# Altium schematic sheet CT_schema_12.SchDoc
size 382 x 278 mm
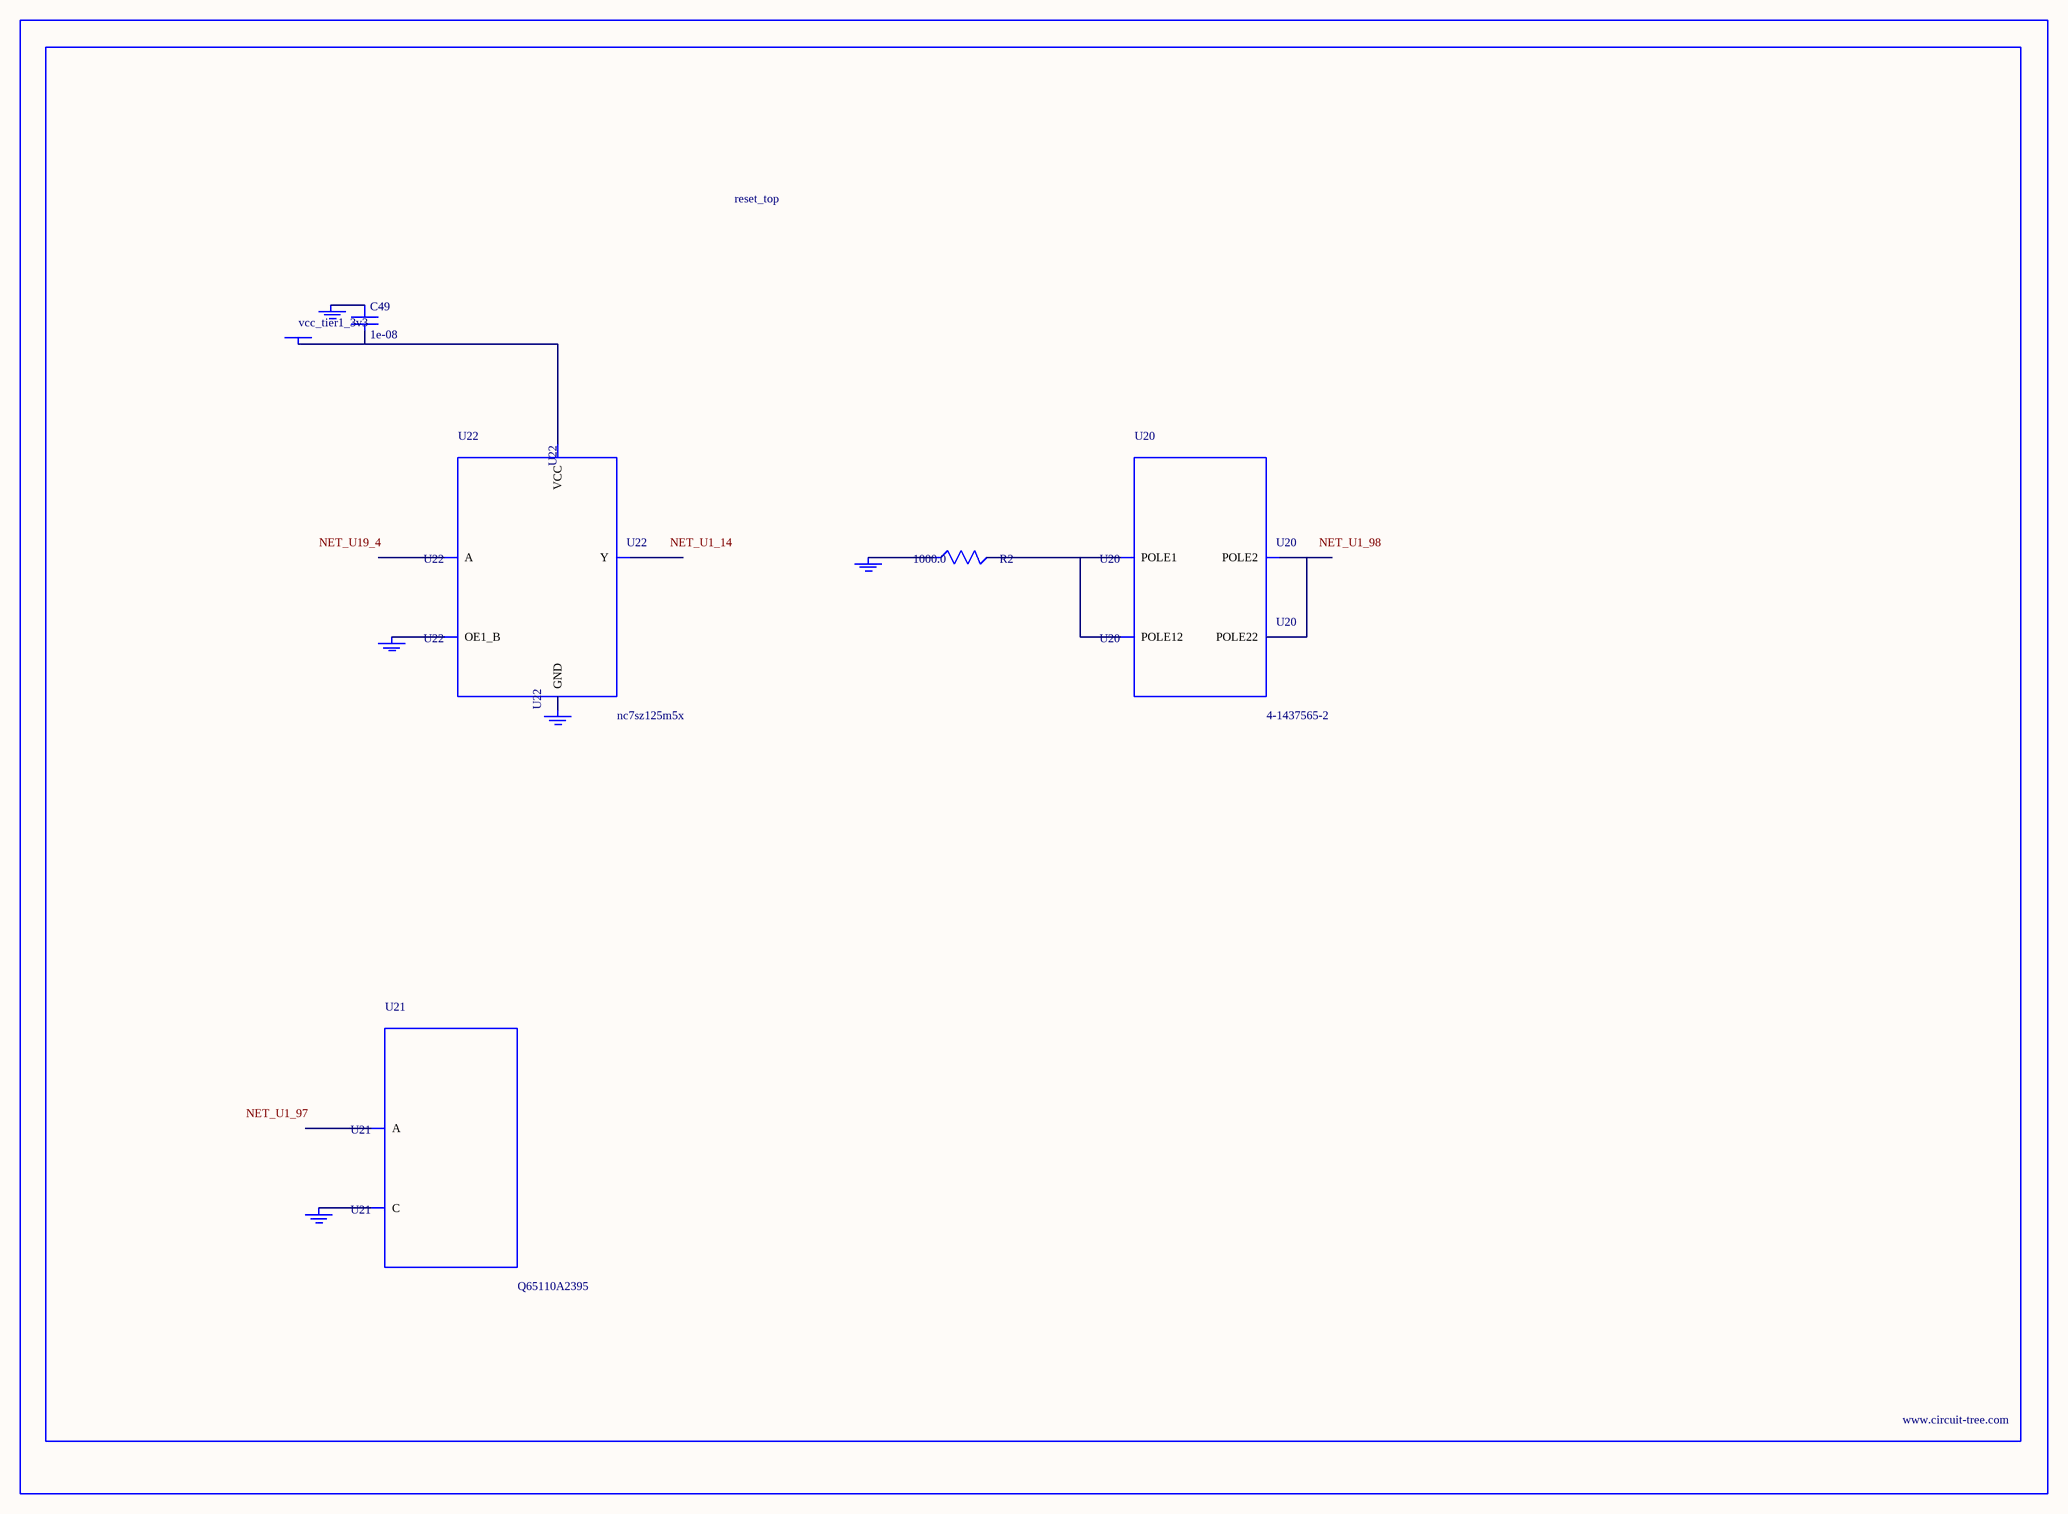
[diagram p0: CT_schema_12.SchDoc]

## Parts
BORDER11  (no value)
C49  1e-08  [C0402]
GND_INSTANCE_11_0  (no value)
GND_INSTANCE_11_1  (no value)
GND_INSTANCE_11_2  (no value)
GND_INSTANCE_11_3  (no value)
GND_INSTANCE_11_4  (no value)
POWER_INSTANCE_11_0  vcc_tier1_3v3
R2  1000.0  [R0603]
U20  4-1437565-2  [SW_4-1437565-2]
U21  Q65110A2395  [LGM67K-G1J2-24-Z]
U22  nc7sz125m5x  [NC7SZ125M5X]

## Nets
NetC49_1: C49.1 GND_INSTANCE_11_2.0(GND)
NetC49_2: C49.2 POWER_INSTANCE_11_0.0(PWR) U22.5(VCC)
NetGND_INSTANCE_11_0_0: GND_INSTANCE_11_0.0(GND) R2.1
NetGND_INSTANCE_11_1_0: GND_INSTANCE_11_1.0(GND) U21.C
NetGND_INSTANCE_11_3_0: GND_INSTANCE_11_3.0(GND) U22.1(OE1_B)
NetGND_INSTANCE_11_4_0: GND_INSTANCE_11_4.0(GND) U22.3(GND)
NetR2_2: R2.2 U20.1(POLE1) U20.2(POLE12)
NetU20_3: U20.3(POLE2) U20.4(POLE22)

Not connected (* = marked no-connect by the designer): U21 A; U22 2(A) 4(Y)

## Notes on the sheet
- Labels drawn without touching a wire or pin: NET_U1_14, NET_U1_97, NET_U1_98, NET_U19_4

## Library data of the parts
BORDER11 = BORDER_PAGE11
C49 = C0402C103K3RAC
GND_INSTANCE_11_0-GND_INSTANCE_11_4 = GND
POWER_INSTANCE_11_0 = PWR
R2 = RC0603JR-071KL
